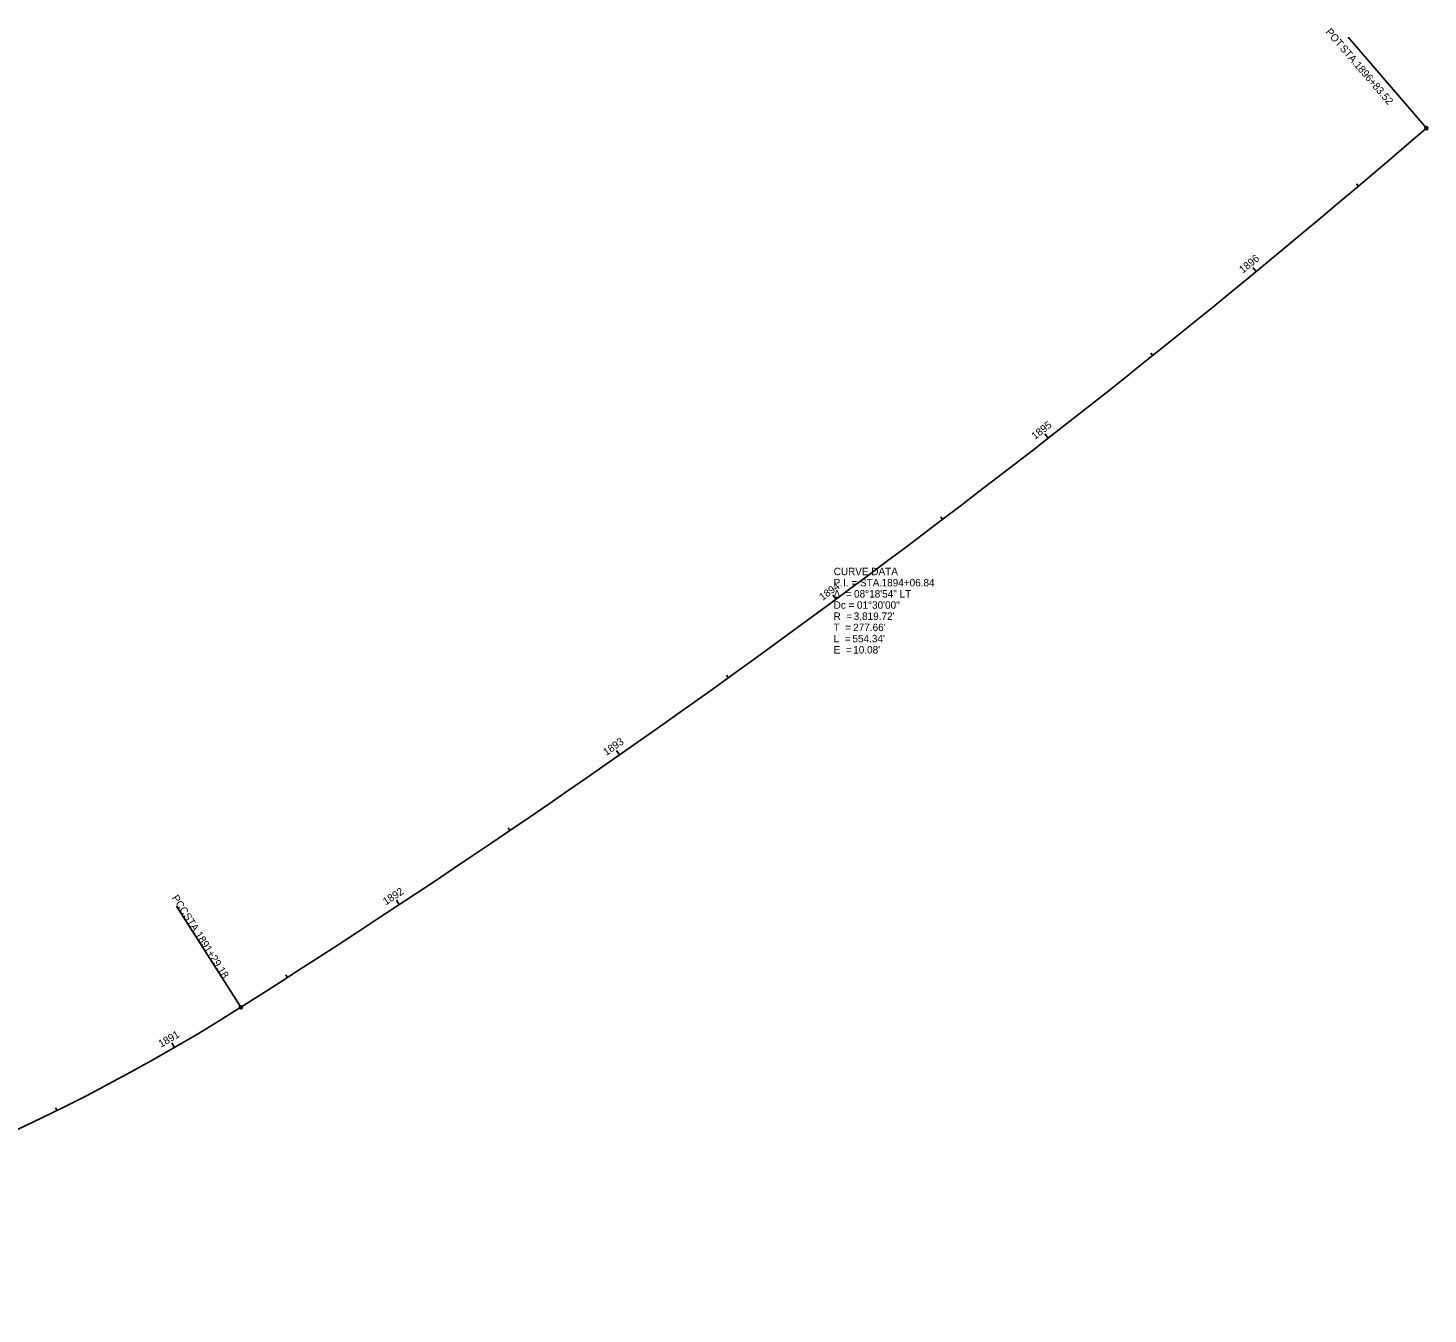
# Model space of a CAD drawing. Extents: x 199310 to 201359, y 391748 to 392909.
# Drawn here: x 200834 to 201359, y 392426 to 392909 of the extents above; entities that cross this region are included whole.
import ezdxf

# ---------------------------------------------------------------- set-up
doc = ezdxf.new("R2010")
doc.units = 0
for name, color, linetype in [('GE_X_Alignment_1000_Stations', 7, 'Continuous'), ('GE_X_Alignment_100_Stations', 7, 'Continuous'), ('GE_X_Alignment_500_Curve_Data', 7, 'Continuous'), ('GE_X_Alignment_500_Stations', 7, 'Continuous')]:
    doc.layers.add(name, color=color, linetype=linetype)

msp = doc.modelspace()

# ---------------------------------------------------------------- linework, layer by layer
at = {"layer": 'GE_X_Alignment_1000_Stations'}
for p, q in [((201333.28, 392849.58), (201332.51, 392850.49)), ((201294.9, 392817.54), (201293.62, 392819.08)), ((201256.09, 392786.01), (201255.34, 392786.95)), ((201216.88, 392754.99), (201215.65, 392756.57)), ((201177.26, 392724.49), (201176.53, 392725.44)), ((201137.25, 392694.51), (201136.06, 392696.11)), ((201096.84, 392665.05), (201096.14, 392666.03)), ((201056.06, 392636.13), (201054.91, 392637.77)), ((201014.9, 392607.74), (201014.23, 392608.73)), ((200973.37, 392579.89), (200972.27, 392581.56)), ((200931.48, 392552.59), (200930.84, 392553.6)), ((200889, 392526.24), (200888, 392527.97)), ((200844.95, 392502.61), (200844.42, 392503.68))]:
    msp.add_line(p, q, dxfattribs=at)
at = {"layer": 'GE_X_Alignment_100_Stations'}
for centre, radius, start, end in [((198866.83, 395766.23), 3819.72, 302.40716, 310.72226), ((200517.72, 393165.55), 739.3, 255.51964, 302.40716)]:
    msp.add_arc(centre, radius, start, end, dxfattribs=at)
at = {"layer": 'GE_X_Alignment_500_Stations'}
for p, q in [((201358.78, 392871.33), (201329.43, 392905.44)), ((200913.94, 392541.38), (200889.82, 392579.38))]:
    msp.add_line(p, q, dxfattribs=at)
for centre in [(201358.78, 392871.33), (200913.94, 392541.38)]:
    msp.add_circle(centre, 0.6, dxfattribs=at)

# ---------------------------------------------------------------- texts
at = {"layer": 'GE_X_Alignment_1000_Stations'}
for s, rotation, p in [('1896', 39.4695, (201289.93, 392816.69)), ('1895', 37.9695, (201211.93, 392754.3)), ('1894', 36.4695, (201132.22, 392693.9)), ('1893', 34.9695, (201051.09, 392635.7)), ('1892', 33.4695, (200968.38, 392579.59)), ('1891', 30.1457, (200883.99, 392526.22))]:
    msp.add_text(s, height=2.8, rotation=rotation, dxfattribs=at).set_placement(p)
at = {"layer": 'GE_X_Alignment_500_Curve_Data'}
for s, p in [('CURVE DATA', (201136.36, 392703.56)), ('P.I. = STA. ', (201136.36, 392699.36)), ('1894+06.84', (201154.35, 392699.36)), ('Δ  = ', (201136.36, 392695.16)), ('08°18\'54" LT', (201144.01, 392695.16)), ('Dc = ', (201136.36, 392690.96)), ('R  = ', (201136.36, 392686.76)), ("3,819.72'", (201143.9, 392686.76)), ('01°30\'00"', (201145.11, 392690.96)), ('T  = ', (201136.36, 392682.56)), ("277.66'", (201143.68, 392682.56)), ('L  = ', (201136.36, 392678.36)), ("554.34'", (201143.4, 392678.36)), ('E  = ', (201136.36, 392674.16)), ("10.08'", (201143.7, 392674.16))]:
    msp.add_text(s, height=2.8, dxfattribs=at).set_placement(p)
at = {"layer": 'GE_X_Alignment_500_Stations'}
for s, rotation, p in [('POT', 310.7223, (201320.78, 392907.35)), (' STA. ', 310.7223, (201325.43, 392901.95)), ('1896+83.52', 310.7223, (201331.51, 392894.88)), ('PCC', 302.4072, (200887.91, 392582.45)), (' STA. ', 302.4072, (200891.64, 392576.57)), ('1891+29.18', 302.4072, (200896.64, 392568.7))]:
    msp.add_text(s, height=2.8, rotation=rotation, dxfattribs=at).set_placement(p)

doc.saveas('drawing.dxf')
